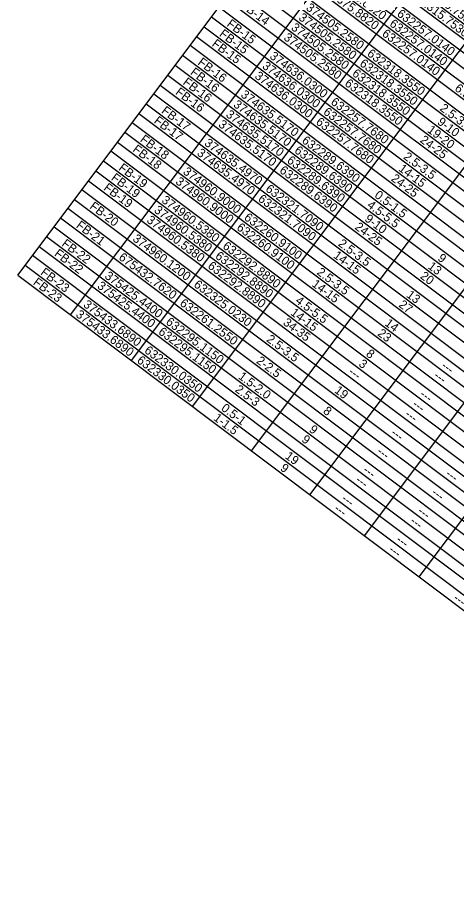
# Model space of a CAD drawing. Extents: x 627484.2 to 627517.5, y 367968.7 to 367996.9.
# Drawn here: x 627484.17 to 627486.93, y 367988.57 to 367994.12 of the extents above; entities that cross this region are included whole.
import ezdxf

# ---------------------------------------------------------------- set-up
doc = ezdxf.new("R2010")
doc.units = 0
doc.layers.add('Default', color=7, linetype='Continuous')

msp = doc.modelspace()

# ---------------------------------------------------------------- linework, layer by layer
at = {"layer": 'Default'}
for p, q in [((627486.383, 367993.955), (627488.192, 367996.3641)), ((627486.7668, 367993.6668), (627488.5759, 367996.0759)), ((627485.943, 367994.8585), (627491.1859, 367990.9215)), ((627485.8961, 367994.7961), (627491.139, 367990.8591)), ((627485.8552, 367994.7415), (627491.0981, 367990.8046)), ((627485.8083, 367994.6791), (627491.0512, 367990.7422)), ((627485.7615, 367994.6168), (627491.0044, 367990.6798)), ((627484.1749, 367992.5039), (627485.7146, 367994.5544)), ((627485.7146, 367994.5544), (627490.9576, 367990.6175)), ((627485.6678, 367994.492), (627490.9107, 367990.5551)), ((627485.621, 367994.4297), (627490.8639, 367990.4927)), ((627485.5741, 367994.3673), (627490.817, 367990.4303)), ((627485.5273, 367994.3049), (627490.7702, 367990.368)), ((627484.5063, 367992.2551), (627485.9992, 367994.2432)), ((627485.4805, 367994.2425), (627490.7234, 367990.3056)), ((627485.4395, 367994.188), (627490.6824, 367990.251)), ((627485.3926, 367994.1256), (627490.6356, 367990.1886)), ((627485.3458, 367994.0632), (627490.5887, 367990.1263)), ((627485.299, 367994.0008), (627490.5419, 367990.0639)), ((627484.8901, 367991.9669), (627486.383, 367993.955)), ((627485.258, 367993.9463), (627490.5009, 367990.0093)), ((627485.2112, 367993.8839), (627490.4541, 367989.9469)), ((627485.1643, 367993.8215), (627490.4072, 367989.8846)), ((627485.1175, 367993.7592), (627490.3604, 367989.8222)), ((627485.0706, 367993.6968), (627490.3136, 367989.7598)), ((627485.0297, 367993.6422), (627490.2726, 367989.7053)), ((627485.2739, 367991.6786), (627486.7668, 367993.6668)), ((627484.9828, 367993.5798), (627490.2257, 367989.6429)), ((627484.936, 367993.5175), (627490.1789, 367989.5805)), ((627484.895, 367993.4629), (627490.1379, 367989.5259)), ((627484.8482, 367993.4005), (627490.0911, 367989.4636)), ((627485.6443, 367991.4005), (627487.1372, 367993.3887)), ((627484.8013, 367993.3381), (627490.0442, 367989.4012)), ((627484.7604, 367993.2836), (627490.0033, 367989.3466)), ((627484.7135, 367993.2212), (627489.9564, 367989.2842)), ((627484.6667, 367993.1588), (627489.9096, 367989.2219)), ((627484.6198, 367993.0964), (627489.8628, 367989.1595)), ((627486.0107, 367991.1254), (627487.5036, 367993.1135)), ((627484.5789, 367993.0419), (627489.8218, 367989.1049)), ((627484.532, 367992.9795), (627489.7749, 367989.0425)), ((627484.491, 367992.9249), (627489.734, 367988.988)), ((627484.4442, 367992.8625), (627489.6871, 367988.9256)), ((627484.4032, 367992.808), (627489.6461, 367988.871)), ((627484.3564, 367992.7456), (627489.5993, 367988.8086)), ((627484.3096, 367992.6832), (627489.5525, 367988.7463)), ((627484.2686, 367992.6286), (627489.5115, 367988.6917)), ((627484.2217, 367992.5663), (627489.4646, 367988.6293)), ((627484.1749, 367992.5039), (627489.4178, 367988.5669)), ((627486.3537, 367990.8678), (627487.39, 367992.2478)), ((627486.6968, 367990.6102), (627487.7331, 367991.9902))]:
    msp.add_line(p, q, dxfattribs=at)

# ---------------------------------------------------------------- texts
for s, p in [('374375.8820', (627486.1222, 367994.3603)), ('632315.7530', (627486.6876, 367994.3137)), ('374375.8820', (627486.0754, 367994.2979)), ('632315.7530', (627486.6407, 367994.2514)), ('FB-14', (627485.5711, 367994.1888)), ('374505.2580', (627485.9817, 367994.1731)), ('374505.2580', (627485.9349, 367994.1108)), ('632257.0140', (627486.5529, 367994.1344)), ('FB-15', (627485.4843, 367994.0711)), ('374505.2580', (627485.8881, 367994.0484)), ('632257.0140', (627486.5061, 367994.072)), ('FB-15', (627485.4375, 367994.0087)), ('374505.2580', (627485.8412, 367993.986)), ('632257.0140', (627486.4592, 367994.0097)), ('FB-15', (627485.3907, 367993.9464)), ('374636.0300', (627485.7534, 367993.8691)), ('632318.3550', (627486.3656, 367993.8849)), ('FB-16', (627485.302, 367993.8301)), ('632318.3550', (627486.3187, 367993.8226)), ('FB-16', (627485.2551, 367993.7677)), ('374636.0300', (627485.7066, 367993.8067)), ('632318.3550', (627486.2719, 367993.7602)), ('FB-16', (627485.2083, 367993.7053)), ('374636.0300', (627485.6597, 367993.7443)), ('FB-16', (627485.1614, 367993.643)), ('632318.3550', (627486.225, 367993.6978)), ('6.5-7.5', (627486.9158, 367993.6668)), ('374635.5170', (627485.5719, 367993.6274)), ('374635.5170', (627485.5251, 367993.565)), ('632257.7680', (627486.1372, 367993.5809)), ('2.5-3.5', (627486.8222, 367993.542)), ('FB-17', (627485.0738, 367993.5259)), ('374635.5170', (627485.4782, 367993.5026)), ('632257.7680', (627486.0904, 367993.5185)), ('FB-17', (627485.027, 367993.4635)), ('374635.5170', (627485.4314, 367993.4403)), ('632257.7680', (627486.0436, 367993.4561)), ('9-10', (627486.8068, 367993.456)), ('19-20', (627486.7437, 367993.4059)), ('FB-18', (627484.9396, 367993.3462)), ('374635.4970', (627485.3436, 367993.3233)), ('632289.6390', (627485.9557, 367993.3392)), ('24-25', (627486.6979, 367993.3427)), ('FB-18', (627484.8928, 367993.2839)), ('374635.4970', (627485.2967, 367993.2609)), ('632289.6390', (627485.9089, 367993.2768)), ('632289.6390', (627485.8621, 367993.2144)), ('2.5-3.5', (627486.5938, 367993.238)), ('FB-19', (627484.8045, 367993.1673)), ('374960.9000', (627485.2089, 367993.144)), ('632289.6390', (627485.8152, 367993.152)), ('14-15', (627486.5632, 367993.1634)), ('FB-19', (627484.7576, 367993.1049)), ('24-25', (627486.5164, 367993.101)), ('FB-19', (627484.7108, 367993.0425)), ('374960.9000', (627485.1621, 367993.0816)), ('632321.7090', (627485.7274, 367993.0351)), ('0.5-1.5', (627486.4124, 367992.9963)), ('FB-20', (627484.6227, 367992.9258)), ('374960.5380', (627485.0743, 367992.9647)), ('632321.7090', (627485.6806, 367992.9727)), ('4.5-5.5', (627486.3655, 367992.9339)), ('374960.5380', (627485.0274, 367992.9023)), ('FB-21', (627484.5378, 367992.8067)), ('374960.5380', (627484.9806, 367992.8399)), ('632260.9100', (627485.5928, 367992.8558)), ('9-10', (627486.3502, 367992.8479)), ('632260.9100', (627485.5459, 367992.7934)), ('24-25', (627486.2881, 367992.797)), ('374960.1200', (627484.8928, 367992.723)), ('FB-22', (627484.4473, 367992.6917)), ('632292.8890', (627485.4581, 367992.6765)), ('2.5-3.5', (627486.184, 367992.6922)), ('FB-22', (627484.4005, 367992.6293)), ('675432.7620', (627484.805, 367992.606)), ('632292.8890', (627485.4113, 367992.6141)), ('14-15', (627486.1534, 367992.6177)), ('9', (627486.8089, 367992.6009)), ('632292.8890', (627485.3644, 367992.5517)), ('13', (627486.7472, 367992.5498)), ('FB-23', (627484.314, 367992.5114)), ('375425.4400', (627484.7171, 367992.4891)), ('2.5-3.5', (627486.0494, 367992.5129)), ('20', (627486.6988, 367992.4886)), ('FB-23', (627484.2672, 367992.449)), ('375425.4400', (627484.6703, 367992.4267)), ('632325.0230', (627485.2766, 367992.4348)), ('14-15', (627486.0188, 367992.4383)), ('13', (627486.6125, 367992.3705)), ('632261.2550', (627485.1888, 367992.3178)), ('4.5-5.5', (627485.9147, 367992.3336)), ('375433.6890', (627484.5825, 367992.3098)), ('14-15', (627485.8841, 367992.259)), ('27', (627486.5644, 367992.309)), ('375433.6890', (627484.5357, 367992.2474)), ('632295.1150', (627485.101, 367992.2009)), ('34-35', (627485.8373, 367992.1966)), ('14', (627486.4763, 367992.1923)), ('632295.1150', (627485.0541, 367992.1385)), ('2.5-3.5', (627485.7332, 367992.0919)), ('23', (627486.431, 367992.1288)), ('632330.0350', (627484.9663, 367992.0215)), ('8', (627486.3586, 367992.0002)), ('632330.0350', (627484.9195, 367991.9592)), ('2-2.5', (627485.6698, 367991.9566)), ('3', (627486.3126, 367991.9372)), ('---', (627486.2482, 367991.8881)), ('---', (627486.8312, 367991.9258)), ('1.5-2.0', (627485.5566, 367991.8587)), ('---', (627486.7844, 367991.8634)), ('2.5-3', (627485.5357, 367991.7769)), ('19', (627486.1604, 367991.7711)), ('---', (627486.6966, 367991.7465)), ('0.5-1', (627485.4491, 367991.659)), ('---', (627486.6497, 367991.6841)), ('1-1.5', (627485.4005, 367991.598)), ('8', (627486.0893, 367991.6416)), ('---', (627486.6029, 367991.6217)), ('9', (627486.001, 367991.525)), ('---', (627486.5151, 367991.5048)), ('9', (627485.9542, 367991.4626)), ('---', (627486.4273, 367991.3878)), ('19', (627485.8501, 367991.3579)), ('9', (627485.8195, 367991.2833)), ('---', (627486.3394, 367991.2709)), ('---', (627486.8581, 367991.2472)), ('---', (627486.2926, 367991.2085)), ('---', (627486.7703, 367991.1302)), ('---', (627486.2048, 367991.0916)), ('---', (627486.158, 367991.0292)), ('---', (627486.6825, 367991.0133)), ('---', (627486.6357, 367990.9509)), ('---', (627486.5478, 367990.834)), ('---', (627486.501, 367990.7716)), ('---', (627486.9064, 367990.4672))]:
    msp.add_text(s, height=0.055, rotation=323.0968, dxfattribs=at).set_placement(p)

doc.saveas('drawing.dxf')
